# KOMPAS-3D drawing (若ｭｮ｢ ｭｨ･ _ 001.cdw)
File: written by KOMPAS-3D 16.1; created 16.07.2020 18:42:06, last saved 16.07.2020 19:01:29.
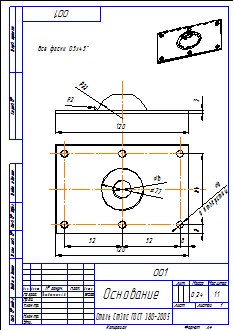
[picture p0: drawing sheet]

Sheet 1: A4, portrait

Title block, sheet 1: name: Основание; designation: 001; material: Сталь Ст3пс ГОСТ 380-2005; mass: 0,24; scale: 1:1; sheets: 1; sheet format: A4; drawn by: Чередниченко А.В.; drawn by, date: 16.17.2020.

Views: Вид 1, Спереди, Вид 2, Сверху, Вид 3, Вид:1
Referenced files in D:\Новая папка\работа\Чертежи\Крюк\: Основание.m3d
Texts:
  user
  Все фаски 0.5х45
Dimensions and other numbers on the sheet: 120; 8; 52; 64; 6; 6 отверстий; 16; 77; 3; 23; 2; 1:1; 1; 0,24; 001; 16.17.2020.; 001-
